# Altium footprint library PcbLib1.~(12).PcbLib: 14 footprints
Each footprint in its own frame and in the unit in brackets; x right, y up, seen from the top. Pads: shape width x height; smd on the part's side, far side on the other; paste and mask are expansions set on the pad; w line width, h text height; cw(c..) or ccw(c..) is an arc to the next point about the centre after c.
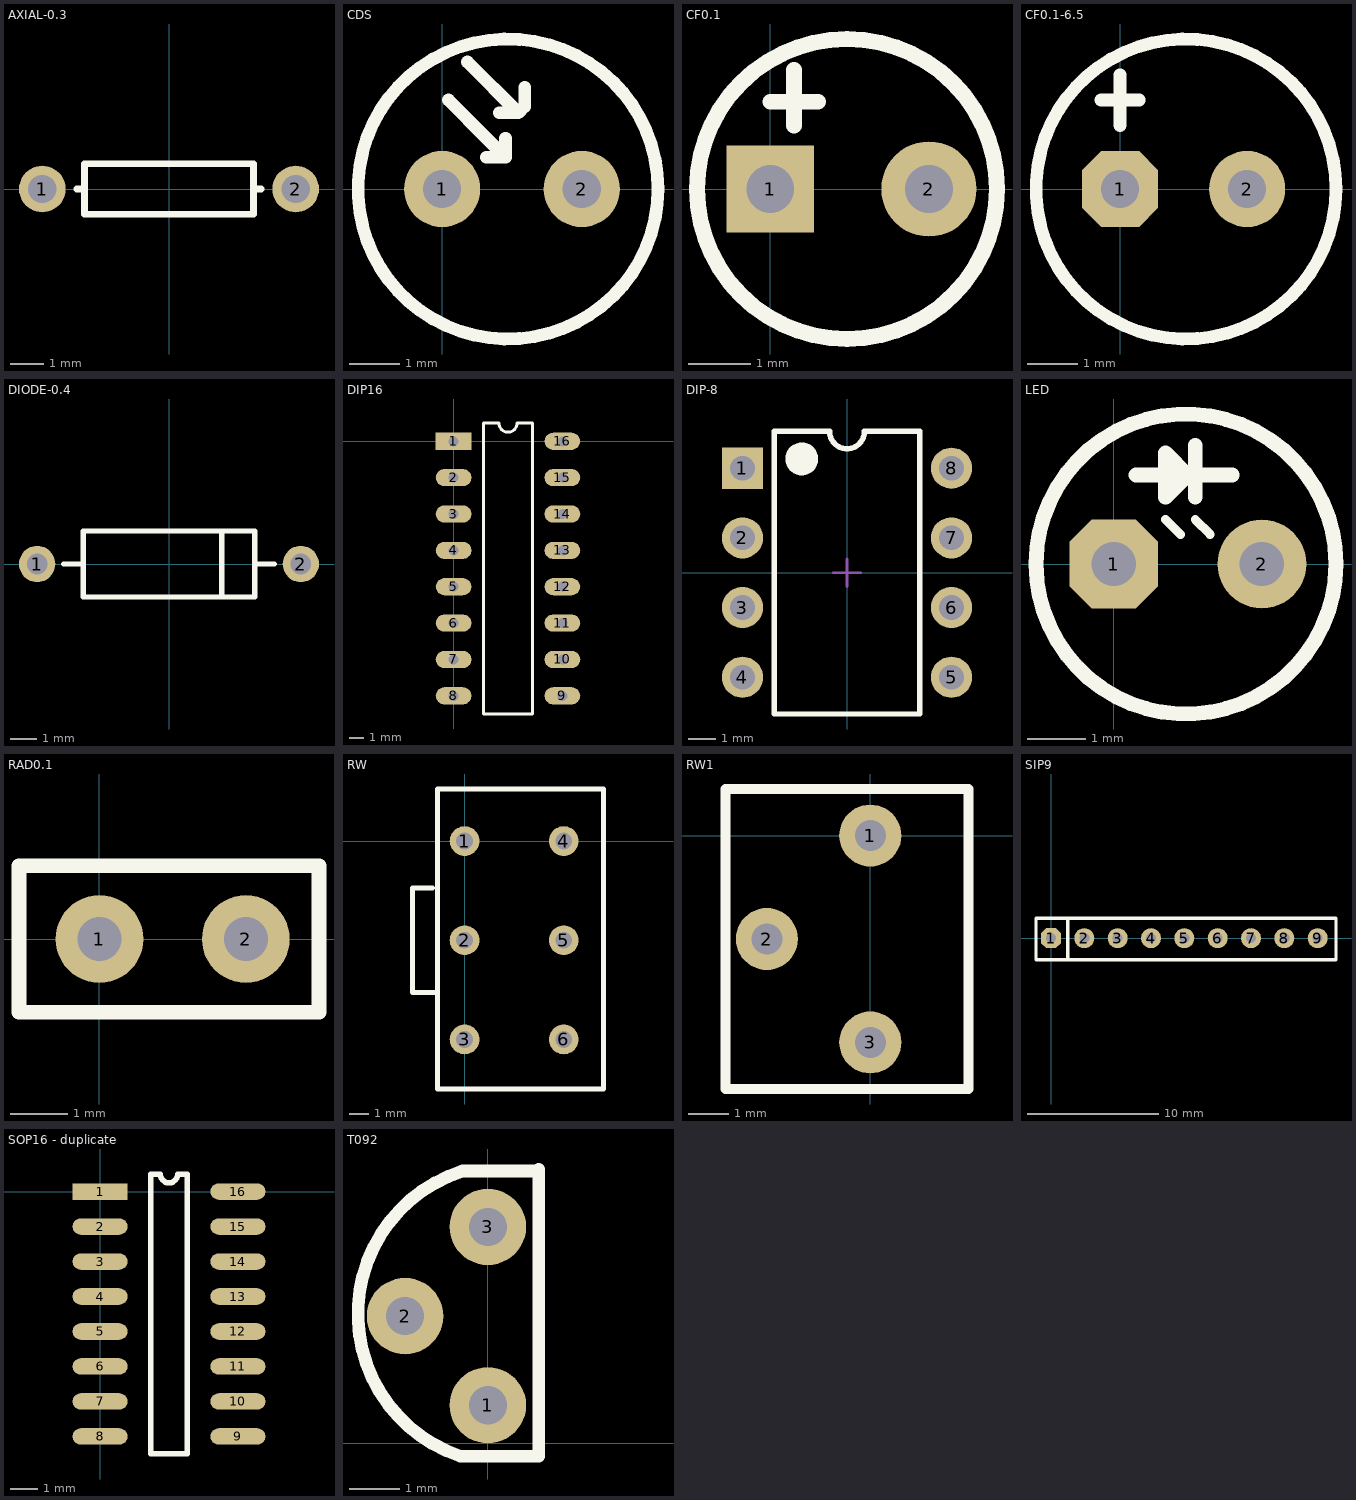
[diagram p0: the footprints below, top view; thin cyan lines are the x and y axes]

## AXIAL-0.3 [mm] "Axial Device, Thru-Hole; 2 Leads; 0.3 in Pin Spacing"
height 1.524
pads (2):
  round 1.4 hole 0.85: 1(-3.81,0) 2(3.81,0)
Top Overlay:
  lines w0.2: -2.769,0 -2.54,0 ; 2.769,0 2.54,0 ; 2.54,0 2.54,0.762 -2.54,0.762 -2.54,-0.762 2.54,-0.762 2.54,0

## CDS [mil]
pads (2):
  round 60 hole 30: 1(0,0) 2(110,0)
Top Overlay:
  circle w10: c51.89,0 r118.11
  lines w10: 5,70 35,40 45,30 50,25 ; 20,100 60,60 ; 35,25 50,25 ; 45,60 60,60 ; 50,40 50,25 ; 65,80 65,65 60,60

## CF0.1 [mil]
pads (2):
  rect 55.12x55.12 hole 30: 1(0,0)
  round 60 hole 30: 2(100,0)
Top Overlay:
  circle w10: c48.39,0 r94.49
  lines w10: 0,55 30,55 ; 15,40 15,75

## CF0.1-6.5 [mil]
pads (2):
  oct 60x60 hole 30: 1(0,0)
  round 60 hole 30: 2(100,0)
Top Overlay:
  circle w10: c51.89,0 r118.11
  lines w10: -15,70 15,70 ; 0,50 0,90

## DIODE-0.4 [mm] "Diode, Thru-Hole; 2 Leads; 0.4 in Pin Spacing"
height 2.54
pads (2):
  round 1.4 hole 0.8: 1(-5.08,0) 2(5.08,0)
Top Overlay:
  lines w0.2: -4.064,0 -3.302,0 ; 2.032,-1.27 2.032,1.27 ; 3.302,0 4.064,0 ; -3.302,-1.27 -3.302,1.27 3.302,1.27 3.302,-1.27 -3.302,-1.27

## DIP16 [mm]
pads (16):
  rect 2.5x1.2 hole 0.7: 1(0,0)
  oval 2.5x1.2 hole 0.7: 2(0,-2.54) 3(0,-5.08) 4(0,-7.62) 5(0,-10.16) 6(0,-12.7) 7(0,-15.24) 8(0,-17.78) 9(7.6,-17.78) 10(7.6,-15.24) 11(7.6,-12.7) 12(7.6,-10.16) 13(7.6,-7.62) 14(7.6,-5.08) 15(7.6,-2.54) 16(7.6,0)
Top Overlay:
  lines w0.2: 2.085,-19.05 5.515,-19.05 5.515,1.27 4.435,1.27 cw(c3.8,1.27) 3.165,1.27 2.085,1.27 2.085,-19.05

## DIP-8 [mm] "DIP; 8 Leads; Row Spacing 7.62 mm; Pitch 2.54 mm"
height 5.08
pads (8):
  rect 1.5x1.5 hole 0.9: 1(-3.81,3.81)
  round 1.5 hole 0.9: 2(-3.81,1.27) 3(-3.81,-1.27) 4(-3.81,-3.81) 5(3.81,-3.81) 6(3.81,-1.27) 7(3.81,1.27) 8(3.81,3.81)
Top Overlay:
  circle w0.6: c-1.65,4.15 r0.3
  lines w0.2: -2.65,-5.15 2.65,-5.15 2.65,5.15 0.635,5.15 cw(c0,5.15) -0.635,5.15 -2.65,5.15 -2.65,-5.15
Mechanical 15:
  lines w0.1: -0.5,0 0.5,0 ; 0,-0.5 0,0.5

## LED [mil]
pads (2):
  oct 60x60 hole 30: 1(0,0)
  round 60 hole 30: 2(100,0)
Top Overlay:
  circle w10: c48.76,0 r101.24
  lines w6.06: 35,30 45,20 ; 55,30 65,20
  lines w10: 15,60 80,60 ; 55,45 55,80 ; 35,45 50,60 35,75 35,45

## RAD0.1 [mil]
pads (2):
  round 60 hole 30: 1(0,0) 2(100,0)
Top Overlay:
  lines w10: -55,-50 150,-50 150,50 -55,50 -55,-50

## RW [mil]
pads (6):
  round 60 hole 33.94: 1(0,0) 2(0,-200) 3(0,-400) 4(200,0) 5(200,-200) 6(200,-400)
Top Overlay:
  lines w10: -65,-95 -105,-95 -105,-305 -55,-305 ; -55,-500 280,-500 280,105 -55,105 -55,-500

## RW1 [mil]
pads (3):
  round 60 hole 30: 1(0,0) 2(-100,-100) 3(0,-200)
Top Overlay:
  lines w10: -140,-245 95,-245 95,45 -140,45 -140,-245

## SIP9 [mil]
pads (9):
  oct 60x60 hole 30: 1(0,0)
  round 60 hole 30: 2(100,0) 3(200,0) 4(300,0) 5(400,0) 6(500,0) 7(600,0) 8(700,0) 9(800,0)
Top Overlay:
  lines w10: 50,-65 50,60 ; -45,-65 -45,60 -35,60 855,60 855,-65 -45,-65

## SOP16 - duplicate [mm]
pads (16):
  rect 2x0.6 smd: 1(0,0)
  oval 2x0.6 smd: 2(0,-1.27) 3(0,-2.54) 4(0,-3.81) 5(0,-5.08) 6(0,-6.35) 7(0,-7.62) 8(0,-8.89) 9(5,-8.89) 10(5,-7.62) 11(5,-6.35) 12(5,-5.08) 13(5,-3.81) 14(5,-2.54) 15(5,-1.27) 16(5,0)
Top Overlay:
  lines w0.2: 1.835,-9.525 3.165,-9.525 3.165,0.635 2.818,0.635 cw(c2.5,0.635) 2.183,0.635 1.835,0.635 1.835,-9.525

## T092 [mil]
pads (3):
  round 60 hole 30: 1(0,30) 2(-65,100) 3(0,170)
Top Overlay:
  lines w10: 38.81,213.81 -20,213.81 ccw(c15.8,101.64) -21.6,-10 40,-10 40,215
